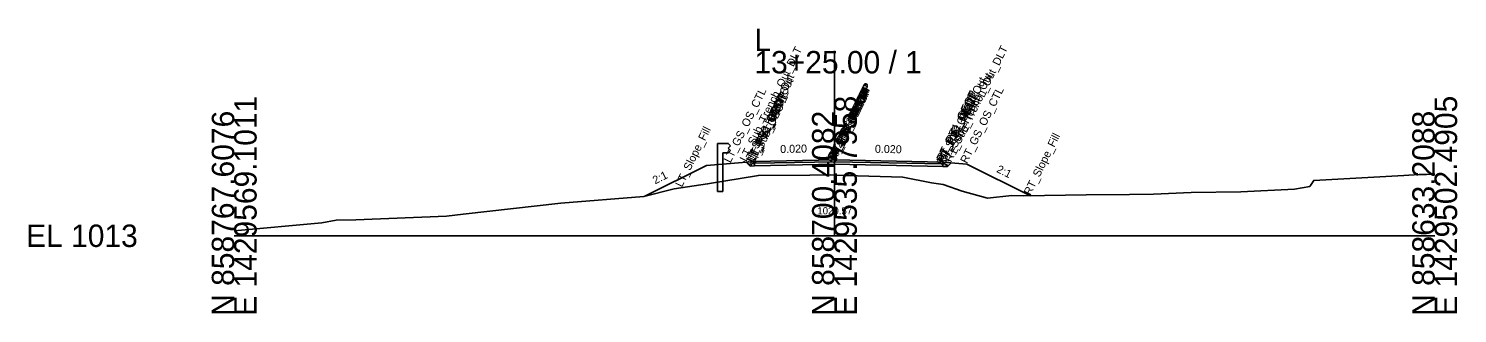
# Model space of a CAD drawing. Extents: x -26 to 153, y -10 to 13058.
# Drawn here: x -25.7 to 152.8, y 3490.3 to 3525.9 of the extents above; entities that cross this region are included whole.
import ezdxf

# ---------------------------------------------------------------- set-up
doc = ezdxf.new("R2010")
doc.units = 0
for name, color, linetype in [('Default', 7, 'Continuous'), ('Exist Cross Section Cell', 7, 'Continuous'), ('Exist XS Ground Line', 7, 'Continuous'), ('Prop CMT Guardrail Widen Shoulder', 7, 'Continuous'), ('Prop CMT Pvmt Course 1', 7, 'Continuous'), ('Prop CMT Pvmt Course 2', 7, 'Continuous'), ('Prop CMT Pvmt Surface', 7, 'Continuous'), ('Prop CMT Pvmt Surface Shoulder', 7, 'Continuous'), ('Prop CMT Shld Paved Course 1', 7, 'Continuous'), ('Prop CMT Shld Paved Course 2', 7, 'Continuous'), ('Prop CMT Slope Grass', 7, 'Continuous'), ('Prop CMT Subgrade Daylight Point', 7, 'Continuous'), ('Prop CMT Subgrade Earthwork', 7, 'Continuous'), ('Prop XS Dump Level', 7, 'Continuous'), ('Prop XS SE Text', 7, 'Continuous'), ('Prop XS Side Slope Text', 7, 'Continuous')]:
    doc.layers.add(name, color=color, linetype=linetype)

msp = doc.modelspace()

# ---------------------------------------------------------------- linework, layer by layer
at = {"layer": 'Exist Cross Section Cell'}
for p, q in [((75, 3500), (75, 3523.07)), ((0, 3500), (75, 3500)), ((75, 3500), (150, 3500))]:
    msp.add_line(p, q, dxfattribs=at)
at = {"layer": 'Exist XS Ground Line'}
msp.add_lwpolyline([(0, 3500.63), (10.95, 3501.62), (12.76, 3501.93), (15.19, 3501.99), (26.51, 3502.45), (28.61, 3502.69), (40.82, 3504.05), (51.18, 3504.89), (54.99, 3505.85), (59.14, 3506.47), (65.51, 3507.54), (71.91, 3507.57), (74.5, 3507.59), (75, 3507.57), (77.88, 3507.47), (83.56, 3507.3), (87.14, 3506.59), (88.59, 3506.42), (90.94, 3505.58), (94.13, 3504.68), (97.18, 3505.04), (98.65, 3504.97), (106.47, 3505.13), (111.87, 3505.15), (114.85, 3505.18), (119.59, 3505.42), (125.78, 3505.49), (132.49, 3505.83), (134.38, 3506.16), (134.88, 3506.91), (146.13, 3507.52), (148.08, 3507.63), (148.97, 3507.63), (150, 3507.69)], dxfattribs=at)
at = {"layer": 'Prop CMT Guardrail Widen Shoulder'}
msp.add_line((60.4, 3505.52), (61.06, 3505.52), dxfattribs=at)
for points in [[(60.4, 3505.52), (60.4, 3511.52)], [(60.4, 3511.52), (61.73, 3511.52), (62, 3511.23)], [(62, 3510.65), (61.73, 3510.35), (61.06, 3510.35)], [(61.06, 3510.35), (61.06, 3505.52)], [(62, 3511.23), (61.73, 3510.94)], [(61.73, 3510.94), (62, 3510.65)]]:
    msp.add_lwpolyline(points, dxfattribs=at)
at = {"layer": 'Prop CMT Pvmt Course 1'}
for points in [[(75, 3509.46), (65, 3509.26)], [(65, 3509.26), (65, 3509.05)], [(65, 3509.05), (75, 3509.25)], [(75, 3509.25), (75, 3509.46)], [(75, 3509.46), (88.56, 3509.19)], [(75, 3509.25), (75, 3509.46)], [(88.56, 3508.98), (75, 3509.25)], [(88.56, 3509.19), (88.56, 3508.98)]]:
    msp.add_lwpolyline(points, dxfattribs=at)
msp.add_lwpolyline([(75, 3509.25), (75, 3509.34), (75, 3509.34), (75, 3509.25)], close=True, dxfattribs=at)
msp.add_lwpolyline([(75, 3509.25), (75, 3509.34), (75, 3509.34), (75, 3509.25)], close=True, dxfattribs=at)
at = {"layer": 'Prop CMT Pvmt Course 2'}
for points in [[(75, 3509.25), (65, 3509.05)], [(65, 3509.05), (65, 3508.72)], [(65, 3508.72), (75, 3508.92)], [(75, 3508.92), (75, 3509.25)], [(75, 3508.92), (75, 3509.25)], [(75, 3509.25), (88.56, 3508.98)], [(88.56, 3508.65), (75, 3508.92)], [(88.56, 3508.98), (88.56, 3508.65)]]:
    msp.add_lwpolyline(points, dxfattribs=at)
at = {"layer": 'Prop CMT Pvmt Surface'}
for points in [[(75, 3509.46), (65, 3509.26)], [(75, 3509.46), (88.56, 3509.19)]]:
    msp.add_lwpolyline(points, dxfattribs=at)
at = {"layer": 'Prop CMT Pvmt Surface Shoulder'}
for points in [[(65, 3509.26), (65, 3509.26)], [(88.56, 3509.19), (88.56, 3509.19)]]:
    msp.add_lwpolyline(points, dxfattribs=at)
at = {"layer": 'Prop CMT Shld Paved Course 1'}
for points in [[(65, 3509.26), (64.79, 3509.05)], [(64.79, 3509.05), (65, 3509.05)], [(65, 3509.26), (65, 3509.26)], [(65, 3509.05), (65, 3509.26)], [(88.56, 3509.19), (88.56, 3509.19)], [(88.56, 3509.19), (88.78, 3508.98)], [(88.56, 3508.98), (88.56, 3509.19)], [(88.78, 3508.98), (88.56, 3508.98)]]:
    msp.add_lwpolyline(points, dxfattribs=at)
at = {"layer": 'Prop CMT Shld Paved Course 2'}
for points in [[(64.79, 3509.05), (64.45, 3508.71)], [(64.45, 3508.71), (65, 3508.72)], [(65, 3509.05), (64.79, 3509.05)], [(64.79, 3509.05), (64.79, 3509.05)], [(65, 3508.72), (65, 3509.05)], [(88.56, 3508.98), (88.78, 3508.98)], [(88.56, 3508.65), (88.56, 3508.98)], [(89.12, 3508.64), (88.56, 3508.65)], [(88.78, 3508.98), (88.78, 3508.98)], [(88.78, 3508.98), (89.12, 3508.64)]]:
    msp.add_lwpolyline(points, dxfattribs=at)
at = {"layer": 'Prop CMT Slope Grass'}
for points in [[(65, 3509.26), (59, 3508.78), (51.22, 3504.89)], [(88.56, 3509.19), (91.56, 3508.95), (99.49, 3504.98)]]:
    msp.add_lwpolyline(points, dxfattribs=at)
at = {"layer": 'Prop CMT Subgrade Earthwork'}
for points in [[(64.45, 3508.71), (63.98, 3509.18)], [(65, 3508.72), (64.45, 3508.71)], [(75, 3508.92), (65, 3508.72)], [(75, 3508.92), (88.56, 3508.65)], [(88.56, 3508.65), (89.12, 3508.64)], [(89.12, 3508.64), (89.59, 3509.11)]]:
    msp.add_lwpolyline(points, dxfattribs=at)

# ---------------------------------------------------------------- texts
at = {"layer": 'Default'}
msp.add_text('-', height=0.0001, dxfattribs=at).set_placement((0, 3500))
at = {"layer": 'Exist Cross Section Cell'}
for s, p in [('L', (65, 3523.07)), ('13+25.00 / 1', (65, 3520.27)), ('EL 1013', (-26, 3498.6))]:
    msp.add_text(s, height=2.8, dxfattribs=at).set_placement(p)
for s, p in [('E 1429569.1011', (2.8, 3490)), ('E 1429535.7958', (77.8, 3490)), ('E 1429502.4905', (152.8, 3490)), ('N 858767.6076', (0, 3490)), ('N 858700.4082', (75, 3490)), ('N 858633.2088', (150, 3490))]:
    msp.add_text(s, height=2.8, rotation=90, dxfattribs=at).set_placement(p)
at = {"layer": 'Prop CMT Subgrade Daylight Point'}
msp.add_text('1020.57', height=0.9, dxfattribs=at).set_placement((72.86, 3502.67))
at = {"layer": 'Prop XS Dump Level'}
for s, p in [('LT_Sub_Trench_Out_DLT', (63.98, 3509.18)), ('RT_Sub_Trench_Out_DLT', (89.59, 3509.11)), ('LT_Sub_Trench_Out', (64.45, 3508.71)), ('LT_PS2_Shelf_Out', (64.79, 3509.05)), ('RT_PV1_OEEOP', (75, 3509.34)), ('RT_PV2_OEEOP', (75, 3509.25)), ('LT_PV1_OEEOP', (75, 3509.34)), ('RT_PS2_Shelf_Out', (88.78, 3508.98)), ('RT_Sub_Trench_Out', (89.12, 3508.64)), ('LT_GS_OS_CTL', (62, 3509.02)), ('LT_PS2_OEOP', (64.79, 3509.05)), ('LT_PV1_OEOT', (65, 3509.26)), ('LT_PS1_OEOP', (65, 3509.26)), ('LT_PV2_OEOT', (65, 3509.05)), ('LT_Sub_OEOT', (65, 3508.72)), ('LT_PV2_OEEOP', (75, 3509.25)), ('RT_Sub_OEEOP', (75, 3508.92)), ('RT_PV1_IEEOP', (75, 3509.34)), ('RT_PV2_IEEOP', (75, 3509.25)), ('LT_Sub_OEEOP', (75, 3508.92)), ('LT_PV1_IEEOP', (75, 3509.34)), ('LT_PV2_IEEOP', (75, 3509.25)), ('RT_PV1_OEOT', (88.56, 3509.19)), ('RT_PS1_OEOP', (88.56, 3509.19)), ('RT_PV2_OEOT', (88.56, 3508.98)), ('RT_Sub_OEOT', (88.56, 3508.65)), ('RT_PS2_OEOP', (88.78, 3508.98)), ('RT_GS_OS_CTL', (91.56, 3508.95)), ('LT_Slope_Fill', (55.94, 3505.99)), ('PV1_PGL', (75, 3509.46)), ('PV2_PGL', (75, 3509.25)), ('RT_Slope_Fill', (99.49, 3504.98))]:
    msp.add_text(s, height=1, rotation=63.5833, dxfattribs=at).set_placement(p)
at = {"layer": 'Prop XS SE Text'}
for rotation, p in [(1.1458, (68.23, 3510.33)), (358.8542, (80.05, 3510.36))]:
    msp.add_text('0.020', height=1, rotation=rotation, dxfattribs=at).set_placement(p)
at = {"layer": 'Prop XS Side Slope Text'}
for rotation, p in [(333.4349, (95.16, 3507.99)), (26.5651, (52.59, 3506.41))]:
    msp.add_text('2:1', height=1, rotation=rotation, dxfattribs=at).set_placement(p)

doc.saveas('drawing.dxf')
